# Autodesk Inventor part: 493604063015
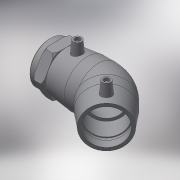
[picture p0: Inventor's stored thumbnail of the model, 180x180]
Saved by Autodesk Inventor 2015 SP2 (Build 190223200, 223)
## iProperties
Created: 2017-06
Part Number: 493604063015
Material: Generic
Description: PLASSON 45° ELBOW TRANSITION FEMALE 63-1.1/2"
Document SubType Name: Modeling
Designer: KIM
Mass: 458.15 g
Surface Area: 867.722 cm^2
Volume: 458.15 cm^3
Density: 1 g/cm^3
Appearance: Default
Author: KIM
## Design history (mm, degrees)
derived "493604.ipt"
feature "Solid1::493604.ipt"
tag "TaggingFeature1"
body "Solid1"
other parameters: "d2" = 82, "d4" = 37, "d5" = 73.8, "d8" = 168 deg, "d10" = 22.8, "d11" = 7.6, "d29" = 59, "d30" = 15, "d31" = 51.8, "d34" = 5 deg, "d41" = 4, "d42" = 14, "d43" = 0, "d49" = 63, "d50" = 53.55, "d51" = 22.8, "d52" = 57, "d54" = 135 deg, "d86" = 36.9, "d87" = 135 deg, "d88" = 148, "d90" = 57, "d91" = 0, "d92" = 57, "d93" = 0, "d101" = 3, "d102" = 0, "d107" = 0.1, "d108" = 48, "d112" = 73.8, "d113" = 44.845, "d114" = 27, "d128" = 18, "d129" = 0, "d132" = 3.15, "d133" = 45 deg, "d134" = 45 deg, "d136" = 1.89, "d_" = 63, "L_" = 178, "L_1" = 57, "D_" = 48, "A_" = 59, "d_2" = 12, "Rp_" = 44.845, "D_1" = 82
